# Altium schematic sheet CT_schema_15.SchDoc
size 391 x 385 mm
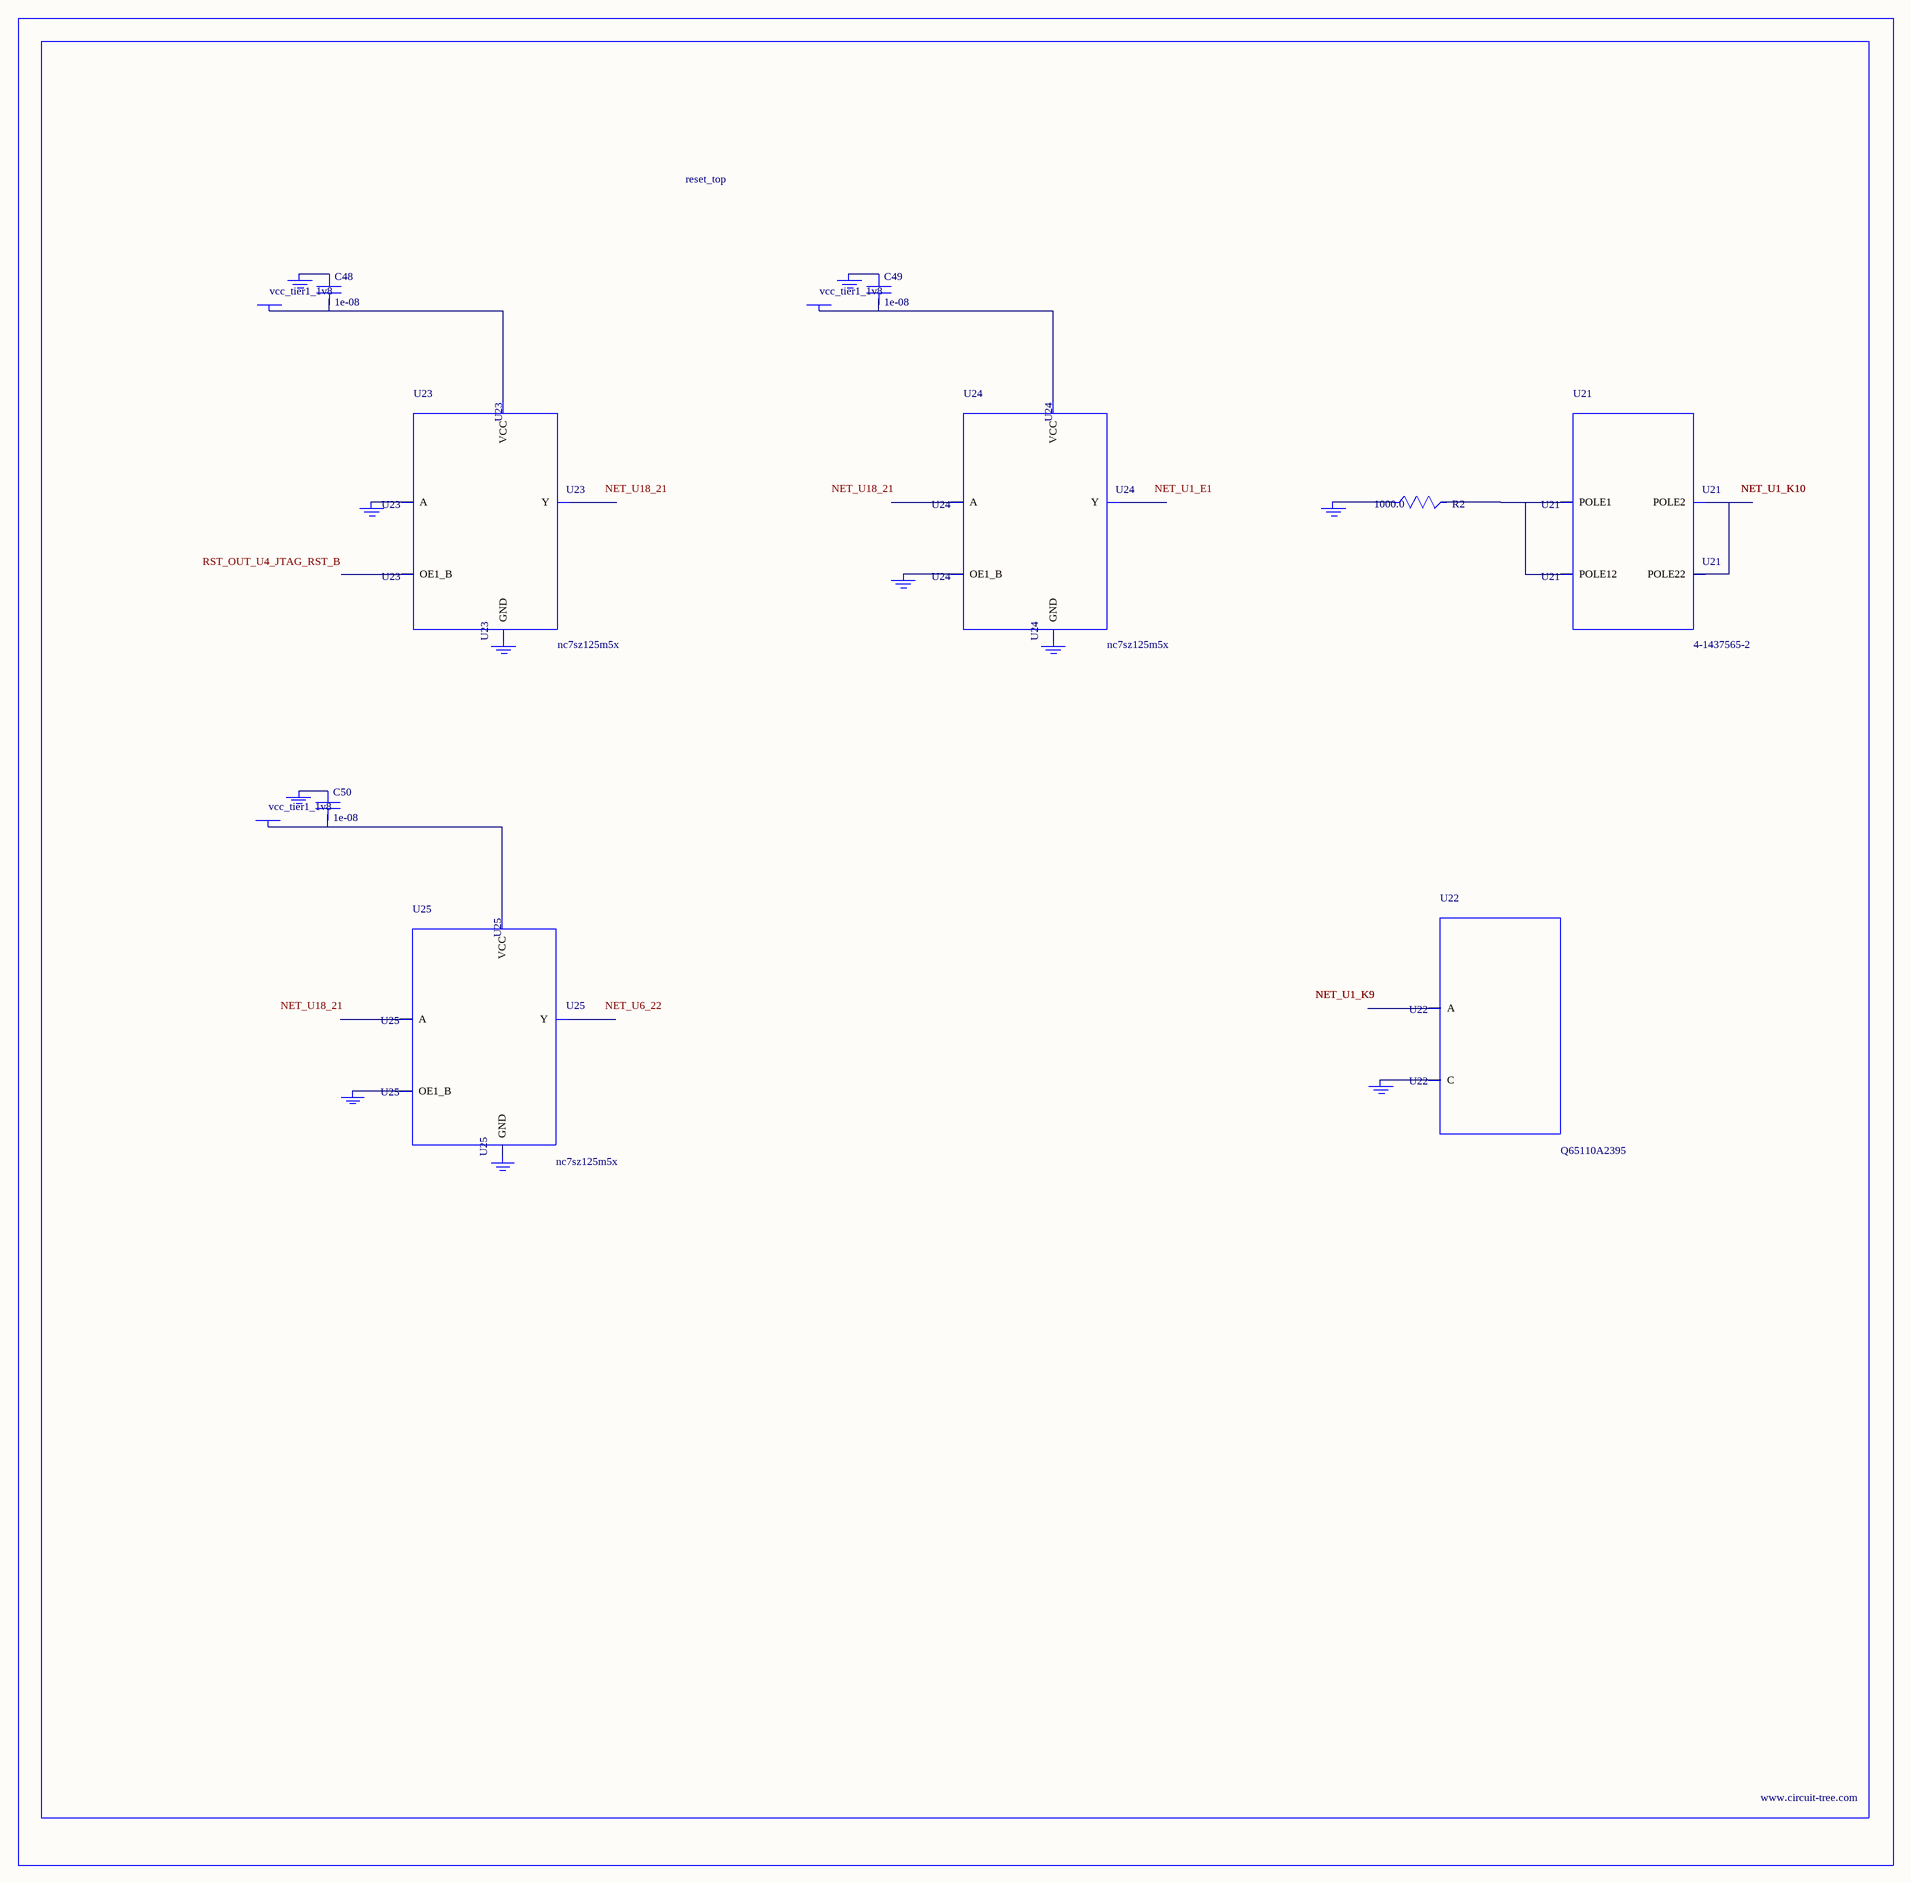
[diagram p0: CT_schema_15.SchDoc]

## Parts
BORDER14  (no value)
C48  1e-08  [C0402]
C49  1e-08  [C0402]
C50  1e-08  [C0402]
GND_INSTANCE_14_0  (no value)
GND_INSTANCE_14_1  (no value)
GND_INSTANCE_14_2  (no value)
GND_INSTANCE_14_3  (no value)
GND_INSTANCE_14_4  (no value)
GND_INSTANCE_14_5  (no value)
GND_INSTANCE_14_6  (no value)
GND_INSTANCE_14_7  (no value)
GND_INSTANCE_14_8  (no value)
GND_INSTANCE_14_9  (no value)
GND_INSTANCE_14_10  (no value)
POWER_INSTANCE_14_0  vcc_tier1_1v8
POWER_INSTANCE_14_1  vcc_tier1_1v8
POWER_INSTANCE_14_2  vcc_tier1_1v8
R2  1000.0  [R0603]
U21  4-1437565-2  [SW_4-1437565-2]
U22  Q65110A2395  [LGM67K-G1J2-24-Z]
U23  nc7sz125m5x  [NC7SZ125M5X]
U24  nc7sz125m5x  [NC7SZ125M5X]
U25  nc7sz125m5x  [NC7SZ125M5X]

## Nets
NetC48_1: C48.1 GND_INSTANCE_14_2.0(GND)
NetC48_2: C48.2 POWER_INSTANCE_14_0.0(PWR) U23.5(VCC)
NetC49_1: C49.1 GND_INSTANCE_14_5.0(GND)
NetC49_2: C49.2 POWER_INSTANCE_14_1.0(PWR) U24.5(VCC)
NetC50_1: C50.1 GND_INSTANCE_14_8.0(GND)
NetC50_2: C50.2 POWER_INSTANCE_14_2.0(PWR) U25.5(VCC)
NetGND_INSTANCE_14_0_0: GND_INSTANCE_14_0.0(GND) R2.1
NetGND_INSTANCE_14_1_0: GND_INSTANCE_14_1.0(GND) U22.C
NetGND_INSTANCE_14_3_0: GND_INSTANCE_14_3.0(GND) U23.2(A)
NetGND_INSTANCE_14_4_0: GND_INSTANCE_14_4.0(GND) U23.3(GND)
NetGND_INSTANCE_14_6_0: GND_INSTANCE_14_6.0(GND) U24.1(OE1_B)
NetGND_INSTANCE_14_7_0: GND_INSTANCE_14_7.0(GND) U24.3(GND)
NetGND_INSTANCE_14_9_0: GND_INSTANCE_14_9.0(GND) U25.1(OE1_B)
NetGND_INSTANCE_14_10_0: GND_INSTANCE_14_10.0(GND) U25.3(GND)
NetR2_2: R2.2 U21.1(POLE1) U21.2(POLE12)
NetU21_3: U21.3(POLE2) U21.4(POLE22)

Not connected (* = marked no-connect by the designer): U22 A; U23 1(OE1_B) 4(Y); U24 2(A) 4(Y); U25 2(A) 4(Y)

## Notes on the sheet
- Labels drawn without touching a wire or pin: NET_U1_E1, NET_U6_22, NET_U18_21, RST_OUT_U4_JTAG_RST_B

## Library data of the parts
BORDER14 = BORDER_PAGE14
C48-C50 = C0402C103K3RAC
GND_INSTANCE_14_0-GND_INSTANCE_14_10 = GND
POWER_INSTANCE_14_0-POWER_INSTANCE_14_2 = PWR
R2 = RC0603JR-071KL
